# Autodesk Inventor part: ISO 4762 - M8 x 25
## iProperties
Comments: To add or edit properties for Autodesk Inventor files, use iProperties.
Created: 2004-03
Part Number: ISO 4762 - M8 x 25
Vendor: Autodesk Inc.
Document SubType Name: Modeling
Designer: rak
Material: Default
Description: Hexagon Socket Head Cap Screw
Standard: ISO 4762
Size Designation: M8 x 25
Alert: To add or edit properties for Autodesk Inventor files, use iProperties.
Control State: 0
Master: False
Checked Out: False
Shininess: 64.0
Length Units: 11269
Angle Units: 11279
Time Units: 11290
Mass Units: 11283
Length Display Precision: 3
Angle Display Precision: 2
Compacted: True
EGR: 1
Density: 0.0
Volumn: 0.0
Area: 0.0
PropertySet Name: Model Information
Author: rak
Revision Number: 8
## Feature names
1. Body [Revolution]
2. Slot [Extrusion]
3. Fillet1
4. Chamfer1
